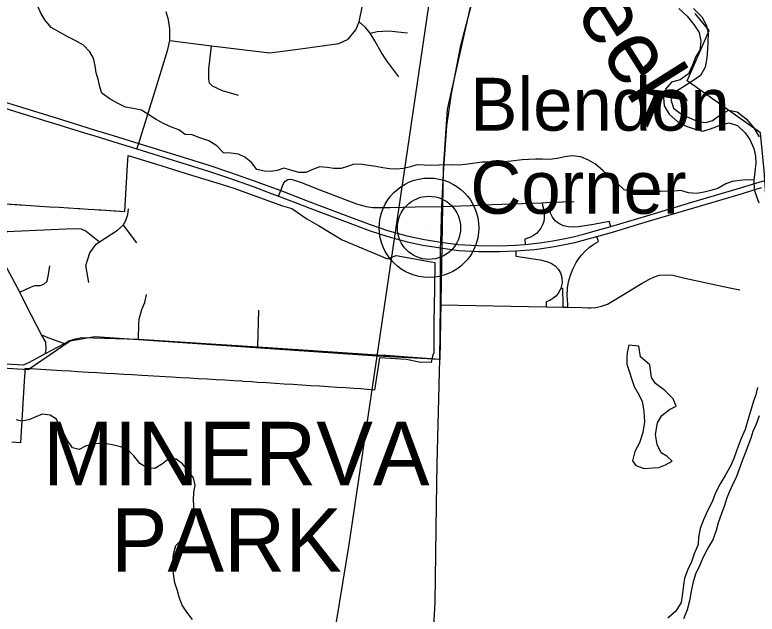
# Model space of a CAD drawing. Extents: x 0 to 34, y 0 to 22.
# Drawn here: x 4.322 to 5.431, y 17.262 to 18.158 of the extents above; entities that cross this region are included whole.
import ezdxf

# ---------------------------------------------------------------- set-up
doc = ezdxf.new("R2010")
doc.units = 0
for name, color, linetype in [('GM_X_City_Street', 7, 'Continuous'), ('GM_X_Corporation', 7, 'Continuous'), ('GM_X_Corporation_Text', 7, 'Continuous'), ('GM_X_County_Road', 7, 'Continuous'), ('GM_X_Interchange_Ramps', 7, 'Continuous'), ('GM_X_Major_River', 7, 'Continuous'), ('GM_X_Major_River_Text', 7, 'Continuous'), ('GM_X_Minor_Lake', 7, 'Continuous'), ('GM_X_Minor_River', 7, 'Continuous'), ('GM_X_Rail_Line', 7, 'Continuous'), ('GM_X_State_Route', 7, 'Continuous'), ('GM_X_Unincorporated', 7, 'Continuous'), ('GM_X_Unincorporated_Location', 7, 'Continuous'), ('GM_X_Unincorporated_Text', 7, 'Continuous')]:
    doc.layers.add(name, color=color, linetype=linetype)

msp = doc.modelspace()

# ---------------------------------------------------------------- linework, layer by layer
at = {"layer": 'GM_X_City_Street'}
for p, q in [((4.4835, 17.8434), (4.5036, 17.8167)), ((4.6848, 17.6616), (4.6864, 17.7161)), ((4.8762, 17.6488), (4.9564, 17.6428))]:
    msp.add_line(p, q, dxfattribs=at)
for points in [[(4.5531, 18.1191), (4.6157, 18.1112), (4.7026, 18.1008), (4.7486, 18.1067), (4.8056, 18.1149), (4.8197, 18.1211), (4.831, 18.1351), (4.836, 18.1472), (4.841, 18.1718), (4.8418, 18.1798), (4.8409, 18.1899), (4.8379, 18.199), (4.8314, 18.2115)], [(4.5042, 17.9572), (4.5069, 17.9656), (4.5119, 17.9816), (4.5348, 18.0557), (4.5503, 18.1058), (4.5531, 18.1191), (4.5532, 18.1367), (4.5514, 18.1504), (4.5477, 18.162)], [(4.8953, 18.0649), (4.8773, 18.0891), (4.8689, 18.1019), (4.8596, 18.119), (4.8524, 18.1303), (4.8455, 18.1387), (4.836, 18.1472)], [(4.8524, 18.1303), (4.863, 18.133), (4.8801, 18.1339), (4.9083, 18.1306)], [(4.6558, 18.0372), (4.6322, 18.0443), (4.6173, 18.051), (4.6127, 18.0556), (4.6115, 18.0616), (4.6114, 18.0764), (4.6157, 18.1112)], [(4.4323, 17.7577), (4.4278, 17.7828), (4.4338, 17.8018), (4.4432, 17.8147), (4.4485, 17.8183), (4.4754, 17.8357), (4.4835, 17.8434), (4.4876, 17.8501), (4.4907, 17.8592), (4.4915, 17.8676)], [(4.3041, 17.8282), (4.3102, 17.8339), (4.3209, 17.8342), (4.4092, 17.8384), (4.4207, 17.838), (4.4284, 17.8345), (4.4485, 17.8183)], [(4.3677, 17.6515), (4.3686, 17.6585), (4.3683, 17.6684), (4.3615, 17.6795), (4.3386, 17.724), (4.3292, 17.743), (4.3031, 17.7926), (4.2987, 17.8089), (4.2999, 17.8203), (4.3041, 17.8282)], [(4.3292, 17.743), (4.3444, 17.7504), (4.3517, 17.753), (4.3596, 17.7529), (4.365, 17.7552), (4.37, 17.7597), (4.3719, 17.7696), (4.3743, 17.7825)], [(4.5067, 17.6731), (4.5072, 17.6961), (4.5074, 17.703), (4.5117, 17.7175), (4.5159, 17.7277), (4.5187, 17.7395)], [(4.1637, 17.6439), (4.3257, 17.6351), (4.3348, 17.6348), (4.3429, 17.638), (4.3677, 17.6515), (4.3959, 17.6667), (4.4027, 17.6704), (4.4126, 17.6736), (4.4217, 17.6756), (4.5067, 17.6731), (4.6848, 17.6616), (4.8712, 17.6491), (4.8762, 17.6488)], [(4.3615, 17.6795), (4.3736, 17.6744), (4.3877, 17.6693), (4.3959, 17.6667)]]:
    msp.add_lwpolyline(points, dxfattribs=at)
at = {"layer": 'GM_X_Corporation'}
for points in [[(6.0874, 17.9568), (6.0027, 17.9627), (5.9083, 17.9706), (5.7991, 17.9758), (5.7562, 17.9753), (5.7213, 17.9698), (5.6189, 17.9397), (5.6023, 17.9358), (5.5774, 17.9293), (5.5387, 17.9169), (5.4879, 17.9006), (5.4786, 17.8937), (5.4653, 17.8843), (5.4439, 17.8811), (5.4411, 17.9254), (5.4406, 17.9301), (5.4357, 17.9811), (5.4171, 17.9943), (5.3261, 18.0588), (5.3588, 18.1342), (5.3379, 18.1599)], [(4.3075, 17.8751), (4.3287, 17.8738), (4.3312, 17.8736), (4.3452, 17.8727), (4.3594, 17.8718), (4.3738, 17.8709), (4.3882, 17.87), (4.402, 17.8691), (4.4163, 17.8682), (4.4187, 17.8681), (4.4312, 17.8673), (4.4415, 17.8666), (4.4472, 17.8663), (4.451, 17.866), (4.4861, 17.8639), (4.4901, 17.9332), (4.4912, 17.9474), (4.54, 17.9323), (4.5792, 17.9202), (4.6301, 17.9045), (4.6488, 17.8987), (4.7217, 17.872), (4.7356, 17.8684), (4.7579, 17.8529), (4.7752, 17.8426), (4.8109, 17.8216), (4.8784, 17.793), (4.8914, 17.798), (4.9437, 17.7885), (4.9493, 17.7875), (4.9485, 17.7487), (4.9475, 17.698), (4.9477, 17.673), (4.9478, 17.6514), (4.9462, 17.6498), (4.9436, 17.638), (4.9258, 17.6387), (4.9064, 17.6426), (4.8663, 17.6451), (4.8592, 17.5968), (4.8483, 17.5979), (4.8384, 17.5985), (4.8282, 17.5992), (4.8158, 17.6), (4.8034, 17.6008), (4.7899, 17.6016), (4.777, 17.6025), (4.7635, 17.6033), (4.7503, 17.6042), (4.7372, 17.605), (4.724, 17.6059), (4.7109, 17.6067), (4.6975, 17.6076), (4.6843, 17.6084), (4.6757, 17.6091), (4.6622, 17.6099), (4.6602, 17.61), (4.649, 17.6107), (4.6357, 17.6115), (4.6224, 17.6123), (4.6092, 17.613), (4.5959, 17.6138), (4.5828, 17.6146), (4.5696, 17.6153), (4.5559, 17.6161), (4.5466, 17.6166), (4.5203, 17.6181), (4.5111, 17.6187), (4.4978, 17.6194), (4.4846, 17.6202), (4.4707, 17.621), (4.4577, 17.6218), (4.4449, 17.6226), (4.4318, 17.6233), (4.4156, 17.6243), (4.4052, 17.6249), (4.3919, 17.6257), (4.337, 17.6289), (4.3367, 17.6237), (4.3358, 17.61), (4.3301, 17.518), (4.3172, 17.5189)], [(4.3075, 17.8751), (4.3254, 17.874), (4.3312, 17.8736), (4.3452, 17.8727), (4.3594, 17.8718), (4.3738, 17.8709), (4.3882, 17.87), (4.402, 17.8691), (4.4163, 17.8682), (4.4187, 17.8681), (4.4312, 17.8673), (4.4415, 17.8666), (4.4472, 17.8663), (4.451, 17.866), (4.4702, 17.8648), (4.4861, 17.8639), (4.4901, 17.9332), (4.4912, 17.9474), (4.54, 17.9323), (4.5792, 17.9202), (4.6301, 17.9045), (4.6488, 17.8987), (4.7217, 17.872), (4.7356, 17.8684), (4.7579, 17.8529), (4.7752, 17.8426), (4.8109, 17.8216), (4.8784, 17.793), (4.8914, 17.798), (4.9437, 17.7885), (4.9493, 17.7875), (4.9485, 17.7487), (4.9475, 17.698), (4.9477, 17.673), (4.9478, 17.6514), (4.9462, 17.6498), (4.9436, 17.638), (4.9258, 17.6387), (4.9064, 17.6426), (4.8663, 17.6451), (4.8592, 17.5968), (4.8483, 17.5979), (4.8384, 17.5985), (4.8282, 17.5992), (4.8158, 17.6), (4.8034, 17.6008), (4.7899, 17.6016), (4.777, 17.6025), (4.7635, 17.6033), (4.7503, 17.6042), (4.7372, 17.605), (4.724, 17.6059), (4.7109, 17.6067), (4.6975, 17.6076), (4.6843, 17.6084), (4.6757, 17.6091), (4.6622, 17.6099), (4.6602, 17.61), (4.649, 17.6107), (4.6357, 17.6115), (4.6224, 17.6123), (4.6092, 17.613), (4.5959, 17.6138), (4.5828, 17.6146), (4.5696, 17.6153), (4.5559, 17.6161), (4.5466, 17.6166), (4.5203, 17.6181), (4.5111, 17.6187), (4.4978, 17.6194), (4.4846, 17.6202), (4.4707, 17.621), (4.4577, 17.6218), (4.4449, 17.6226), (4.4318, 17.6233), (4.4156, 17.6243), (4.4052, 17.6249), (4.3919, 17.6257), (4.337, 17.6289), (4.3367, 17.6237), (4.3358, 17.61), (4.3301, 17.518), (4.3172, 17.5189)]]:
    msp.add_lwpolyline(points, dxfattribs=at)
at = {"layer": 'GM_X_County_Road'}
for p, q in [((5.0024, 17.8727), (5.0345, 17.874)), ((4.9576, 17.7243), (5.1155, 17.7215))]:
    msp.add_line(p, q, dxfattribs=at)
for points in [[(4.7155, 17.8866), (4.719, 17.8952), (4.7232, 17.9054), (4.7255, 17.9089), (4.7296, 17.9114), (4.7341, 17.9119), (4.7408, 17.9102), (4.7484, 17.9074), (4.7776, 17.8963), (4.8135, 17.8823), (4.8324, 17.8754)], [(4.8324, 17.8754), (4.8354, 17.8743), (4.8466, 17.8713), (4.8565, 17.8699), (4.8824, 17.8699), (4.92, 17.8705), (4.9594, 17.8711), (5.0024, 17.8727)], [(5.0345, 17.874), (5.1096, 17.8768), (5.1226, 17.8775), (5.1575, 17.8787)], [(5.178, 17.72), (5.1821, 17.7198), (5.1895, 17.7205), (5.198, 17.7221), (5.2072, 17.7253), (5.2219, 17.7341), (5.259, 17.7564), (5.2686, 17.762), (5.2774, 17.7661), (5.2843, 17.7686), (5.2935, 17.7692), (5.3049, 17.7684), (5.3228, 17.7643), (5.3873, 17.7504), (5.4047, 17.7465)], [(5.1155, 17.7215), (5.1404, 17.721), (5.1479, 17.7208), (5.1687, 17.7203), (5.178, 17.72)]]:
    msp.add_lwpolyline(points, dxfattribs=at)
at = {"layer": 'GM_X_Interchange_Ramps'}
for points in [[(5.1096, 17.8768), (5.1098, 17.8734), (5.1122, 17.8657), (5.1125, 17.8605), (5.1126, 17.8542), (5.112, 17.849), (5.1102, 17.8438), (5.1077, 17.8388), (5.1047, 17.8348), (5.1008, 17.8311), (5.0967, 17.8279), (5.0922, 17.8255), (5.0883, 17.8239), (5.0834, 17.8226), (5.0839, 17.8144)], [(5.2119, 17.8414), (5.2097, 17.8488), (5.186, 17.8444), (5.1638, 17.841), (5.157, 17.8404), (5.1487, 17.8409), (5.1413, 17.8424), (5.1344, 17.8457), (5.1291, 17.85), (5.125, 17.8552), (5.1219, 17.8612), (5.1212, 17.8667), (5.1218, 17.8725), (5.1226, 17.8775)], [(5.1479, 17.7208), (5.1476, 17.7255), (5.1467, 17.7379), (5.1471, 17.7492), (5.1489, 17.7588), (5.1516, 17.7685), (5.1551, 17.7774), (5.1603, 17.7874), (5.1645, 17.7937), (5.1684, 17.7985), (5.1738, 17.8043), (5.1803, 17.8103), (5.1865, 17.815), (5.1934, 17.819), (5.1913, 17.8262)], [(5.0702, 17.805), (5.0704, 17.797), (5.1066, 17.7915), (5.1161, 17.7892), (5.123, 17.7864), (5.129, 17.7827), (5.1336, 17.7778), (5.1368, 17.7722), (5.139, 17.7649), (5.1394, 17.7571), (5.1376, 17.7494), (5.1358, 17.7459), (5.1332, 17.7413), (5.1299, 17.7372), (5.1255, 17.7336), (5.1207, 17.7308), (5.1154, 17.7288), (5.1155, 17.7215)], [(5.1376, 17.7494), (5.1399, 17.7491), (5.1404, 17.7253), (5.1404, 17.721)]]:
    msp.add_lwpolyline(points, dxfattribs=at)
at = {"layer": 'GM_X_Major_River'}
for points in [[(5.3137, 18.1672), (5.3262, 18.1557), (5.336, 18.1431), (5.3442, 18.1313), (5.3465, 18.118), (5.3449, 18.1051), (5.3388, 18.0953), (5.3338, 18.0824), (5.328, 18.0695), (5.3154, 18.0605), (5.3029, 18.0571), (5.2938, 18.0465), (5.2907, 18.034), (5.2917, 18.0215), (5.2993, 18.0093), (5.3121, 17.9978), (5.3246, 17.9913), (5.3382, 17.9867), (5.3488, 17.984), (5.361, 17.9874), (5.3754, 17.993), (5.3887, 17.9964), (5.4012, 17.9925), (5.4125, 17.9811), (5.4197, 17.9715), (5.4257, 17.9578), (5.4283, 17.9464), (5.4286, 17.9362), (5.427, 17.9229), (5.4255, 17.9104), (5.4262, 17.8967), (5.4295, 17.8864), (5.4329, 17.8769)], [(5.3353, 18.1671), (5.3478, 18.1549), (5.3549, 18.1419), (5.3575, 18.1294), (5.3571, 18.1165), (5.3563, 18.1062), (5.3554, 18.0933), (5.3531, 18.0797), (5.3458, 18.0672), (5.3329, 18.0581), (5.3207, 18.0502), (5.3078, 18.0423), (5.3016, 18.0309), (5.3058, 18.0184), (5.3178, 18.0092), (5.3296, 18.0035), (5.3421, 17.9985), (5.3542, 17.9969), (5.3641, 17.9999), (5.3763, 18.0089), (5.3884, 18.015), (5.4009, 18.0126), (5.4142, 18.0023), (5.4258, 17.989), (5.4337, 17.9753)], [(5.4311, 17.6005), (5.4284, 17.5895), (5.425, 17.5801), (5.4211, 17.5668), (5.4169, 17.552), (5.4126, 17.538), (5.4069, 17.5243), (5.4026, 17.5141), (5.3992, 17.5046), (5.3957, 17.4944), (5.3911, 17.4841), (5.3827, 17.469), (5.3754, 17.4565), (5.3685, 17.4432), (5.3632, 17.43), (5.3566, 17.4163), (5.3505, 17.4031), (5.3455, 17.3902), (5.3432, 17.3769), (5.3424, 17.3663), (5.3366, 17.3523), (5.3327, 17.3401), (5.327, 17.3288)], [(5.4336, 17.5584), (5.429, 17.5459), (5.424, 17.5349), (5.4213, 17.525), (5.4174, 17.5144), (5.4136, 17.5049), (5.4082, 17.4909), (5.4036, 17.4788), (5.3998, 17.4678), (5.394, 17.4553), (5.389, 17.4443), (5.3848, 17.4341), (5.3817, 17.4242), (5.3771, 17.4109), (5.3725, 17.3984), (5.3694, 17.387), (5.3644, 17.373), (5.3583, 17.3632), (5.3529, 17.353), (5.3483, 17.3435), (5.3445, 17.334), (5.3387, 17.3219), (5.3349, 17.3105), (5.3321, 17.2965), (5.3294, 17.2817), (5.3263, 17.2684), (5.3206, 17.2548)], [(5.327, 17.3288), (5.322, 17.3155), (5.3204, 17.306), (5.3189, 17.2931), (5.3169, 17.2795), (5.3089, 17.2666), (5.2974, 17.256)]]:
    msp.add_lwpolyline(points, dxfattribs=at)
at = {"layer": 'GM_X_Minor_Lake'}
for points in [[(5.2493, 17.484), (5.2618, 17.4797), (5.2755, 17.4807), (5.2838, 17.481), (5.2937, 17.485), (5.3036, 17.4906), (5.2957, 17.4979), (5.2871, 17.5029), (5.2811, 17.5155), (5.2786, 17.5304), (5.2818, 17.5478), (5.288, 17.5587), (5.2998, 17.5677), (5.3094, 17.5726), (5.3053, 17.584), (5.2929, 17.5963), (5.2786, 17.6067), (5.2726, 17.6158), (5.2701, 17.6345), (5.2566, 17.6467), (5.2541, 17.6627), (5.2389, 17.664), (5.2362, 17.653), (5.2361, 17.645), (5.236, 17.6356)], [(5.2493, 17.484), (5.2618, 17.4797), (5.2755, 17.4807), (5.2838, 17.481), (5.2937, 17.485), (5.3036, 17.4906), (5.2957, 17.4979), (5.2871, 17.5029), (5.2811, 17.5155), (5.2786, 17.5304), (5.2818, 17.5478), (5.288, 17.5587), (5.2998, 17.5677), (5.3094, 17.5726), (5.3053, 17.584), (5.2929, 17.5963), (5.2786, 17.6067), (5.2726, 17.6158), (5.2701, 17.6345), (5.2566, 17.6467), (5.2541, 17.6627), (5.2389, 17.664), (5.2362, 17.653), (5.2361, 17.645), (5.236, 17.6348)], [(5.236, 17.6356), (5.2467, 17.602), (5.2545, 17.5891), (5.259, 17.5799), (5.2611, 17.5651), (5.2621, 17.5495), (5.26, 17.5332), (5.255, 17.5181), (5.248, 17.5052), (5.2445, 17.4912)], [(5.2445, 17.4912), (5.2493, 17.484)]]:
    msp.add_lwpolyline(points, dxfattribs=at)
at = {"layer": 'GM_X_Minor_River'}
for points in [[(4.3665, 18.1501), (4.3609, 18.1604), (4.3557, 18.1715), (4.3517, 18.181), (4.3468, 18.1917), (4.3428, 18.2031), (4.3394, 18.2145), (4.3365, 18.2271), (4.3363, 18.2393), (4.3341, 18.2518), (4.3308, 18.2617), (4.3286, 18.272), (4.3264, 18.2819), (4.3246, 18.2948), (4.3228, 18.3066), (4.3184, 18.3184)], [(5.4255, 17.9106), (5.4142, 17.9112), (5.4047, 17.9101), (5.3933, 17.9087), (5.3838, 17.905), (5.372, 17.8983), (5.3613, 17.895), (5.3515, 17.8928), (5.3401, 17.8906), (5.3283, 17.8915), (5.3166, 17.895), (5.3067, 17.894), (5.2965, 17.8941), (5.2863, 17.8934), (5.2741, 17.8935), (5.2643, 17.8921), (5.2529, 17.8929), (5.2419, 17.8934), (5.2321, 17.8962), (5.2212, 17.9065), (5.2107, 17.9154), (5.2005, 17.9246), (5.1889, 17.9346), (5.1787, 17.9407), (5.1674, 17.9454), (5.1545, 17.947), (5.1431, 17.9456), (5.1317, 17.9431), (5.1203, 17.9413), (5.1097, 17.9418), (5.0999, 17.9422), (5.0896, 17.9416), (5.0798, 17.9409), (5.0631, 17.9392), (5.0517, 17.9381), (5.0422, 17.9386), (5.032, 17.9376), (5.0199, 17.9373), (4.9986, 17.9345), (4.9853, 17.9331), (4.9755, 17.9335), (4.955, 17.933), (4.944, 17.9327), (4.933, 17.9328), (4.9224, 17.9333), (4.9129, 17.9303), (4.9023, 17.9282), (4.8917, 17.9271), (4.8814, 17.9276), (4.8716, 17.9288), (4.861, 17.9312), (4.8508, 17.9325), (4.8406, 17.9341), (4.8284, 17.9346), (4.8189, 17.9312), (4.8091, 17.9279), (4.7984, 17.928), (4.7882, 17.9296), (4.7772, 17.9305), (4.7677, 17.9272), (4.7563, 17.922), (4.7461, 17.9221), (4.734, 17.9256), (4.7234, 17.9287), (4.7139, 17.925), (4.7044, 17.9236), (4.6946, 17.9241), (4.6832, 17.9264), (4.6754, 17.9368), (4.6656, 17.9448), (4.6558, 17.9495), (4.6444, 17.9511), (4.6334, 17.9516), (4.6233, 17.962), (4.6116, 17.9693), (4.598, 17.974), (4.5867, 17.9783), (4.5764, 17.9787), (4.5667, 17.986), (4.5557, 17.9899), (4.544, 17.9954), (4.5331, 18.0012), (4.5218, 18.0081), (4.5112, 18.0154), (4.4987, 18.0178), (4.487, 18.0198), (4.4772, 18.0249), (4.464, 18.0318), (4.4519, 18.0407), (4.4486, 18.0502), (4.4468, 18.0597), (4.4435, 18.0711), (4.4417, 18.0814), (4.4395, 18.0928), (4.4336, 18.1024), (4.4246, 18.1123), (4.4117, 18.1193), (4.4012, 18.1247), (4.3883, 18.1317), (4.3763, 18.1386), (4.3665, 18.1501)], [(4.4695, 17.5145), (4.4593, 17.5165), (4.4476, 17.517), (4.4373, 17.516), (4.4274, 17.513), (4.4179, 17.5082), (4.4081, 17.5106), (4.4006, 17.5216), (4.3954, 17.5316), (4.3887, 17.5426), (4.3842, 17.5533), (4.3744, 17.5595), (4.3627, 17.5607), (4.3532, 17.5567), (4.3429, 17.5526), (4.3319, 17.5504), (4.3236, 17.5524)], [(4.5873, 17.254), (4.5787, 17.2647), (4.5716, 17.2754), (4.5675, 17.2872), (4.5646, 17.2968), (4.5609, 17.3086), (4.5591, 17.3181), (4.558, 17.331), (4.5578, 17.3405), (4.5586, 17.3515), (4.5625, 17.3644), (4.5728, 17.3753), (4.582, 17.3866), (4.5871, 17.3968), (4.5906, 17.4078), (4.5895, 17.4173), (4.5885, 17.4325), (4.5894, 17.4439), (4.591, 17.4545), (4.5888, 17.4659), (4.581, 17.4755), (4.5723, 17.4866), (4.5626, 17.4935), (4.5523, 17.4944), (4.5424, 17.4865), (4.531, 17.4794), (4.52, 17.4799), (4.5087, 17.4872), (4.4997, 17.4987), (4.4895, 17.5083), (4.4797, 17.5122), (4.4695, 17.5145)]]:
    msp.add_lwpolyline(points, dxfattribs=at)
at = {"layer": 'GM_X_Rail_Line'}
for points in [[(4.8023, 17.2505), (4.8213, 17.366), (4.863, 17.6474), (4.9037, 17.9242), (4.9925, 18.5268), (4.995, 18.5559), (4.9836, 19.0836), (4.9859, 19.7538), (4.9926, 19.9029), (5.013, 20.2642), (5.0202, 20.3863), (5.0504, 20.9)], [(5.013, 20.2642), (5.1449, 19.8014), (5.1573, 19.7292), (5.1597, 19.509), (5.1344, 19.0127), (5.1201, 18.6386), (5.0674, 18.4202), (5.0194, 18.2471), (4.9676, 18.0163), (4.9615, 17.9273), (4.9565, 17.6426), (4.863, 17.6474)], [(4.863, 17.6474), (4.4415, 17.6766), (4.4045, 17.6698), (4.3418, 17.6273), (4.1638, 17.6386), (4.1351, 17.6177), (4.0032, 17.5899), (3.7805, 17.5103), (3.7355, 17.4587), (3.7202, 17.4495), (3.6121, 15.7571)]]:
    msp.add_lwpolyline(points, dxfattribs=at)
at = {"layer": 'GM_X_State_Route'}
msp.add_line((4.9564, 17.6428), (4.9576, 17.7243), dxfattribs=at)
for points in [[(4.9594, 17.8711), (4.9619, 17.9208), (4.9669, 17.9919), (4.9742, 18.0398), (4.9879, 18.1116), (5.0132, 18.2094), (5.0472, 18.3361)], [(3.8614, 18.152), (3.8721, 18.1492), (3.9253, 18.1354), (3.9778, 18.1215), (4.0384, 18.1056), (4.0638, 18.0991), (4.1059, 18.0879), (4.1364, 18.0794), (4.1928, 18.0626), (4.2629, 18.041), (4.3202, 18.0232), (4.3838, 18.0037), (4.4388, 17.9865), (4.4689, 17.9772), (4.5069, 17.9656)], [(3.8605, 18.1433), (3.8701, 18.1408), (3.9233, 18.1269), (3.9758, 18.1131), (4.0363, 18.0972), (4.0618, 18.0907), (4.1033, 18.0796), (4.1342, 18.0711), (4.1931, 18.0535), (4.2603, 18.0326), (4.3211, 18.0139), (4.3792, 17.9959), (4.3811, 17.9953), (4.4274, 17.981), (4.44, 17.9772), (4.4696, 17.968), (4.5042, 17.9572), (4.544, 17.9449), (4.5793, 17.9342), (4.6112, 17.9239), (4.641, 17.914), (4.678, 17.9009), (4.7061, 17.8902)], [(4.5069, 17.9656), (4.5474, 17.953), (4.5813, 17.9425), (4.6114, 17.9329), (4.6442, 17.9219), (4.6778, 17.9102), (4.719, 17.8952)], [(4.719, 17.8952), (4.7587, 17.8796), (4.811, 17.8597), (4.8526, 17.8441), (4.8786, 17.8355), (4.9073, 17.8276), (4.9335, 17.8218), (4.958, 17.8179), (4.9841, 17.8142), (5.0139, 17.8127), (5.0453, 17.8125), (5.0696, 17.8135), (5.0839, 17.8144), (5.106, 17.8167), (5.1256, 17.8197), (5.1412, 17.8227), (5.156, 17.8261), (5.1732, 17.8302), (5.1888, 17.8347), (5.2119, 17.8414), (5.2656, 17.8575), (5.3332, 17.8777), (5.4008, 17.8976), (5.445, 17.911)], [(5.239, 17.8403), (5.2484, 17.8432), (5.2683, 17.8491), (5.3359, 17.8692), (5.4035, 17.8893), (5.4373, 17.8996)], [(4.7061, 17.8902), (4.7155, 17.8866), (4.7548, 17.8718)], [(4.7548, 17.8718), (4.7587, 17.8703), (4.8101, 17.8508), (4.8528, 17.8349), (4.8789, 17.8264), (4.9077, 17.8184), (4.9313, 17.8134), (4.9547, 17.8097)], [(4.9577, 17.8024), (4.9578, 17.8092), (4.958, 17.8179), (4.9594, 17.8711)], [(4.9547, 17.8097), (4.9578, 17.8092), (4.9846, 17.8055), (5.0143, 17.804), (5.0457, 17.8038), (5.0702, 17.805), (5.0843, 17.8061), (5.0979, 17.8071), (5.1086, 17.8085), (5.1281, 17.8116), (5.1585, 17.8176), (5.1913, 17.8262), (5.2144, 17.833), (5.239, 17.8403)], [(4.9576, 17.7243), (4.9575, 17.7639), (4.9577, 17.8024)], [(4.9517, 17.4254), (4.9526, 17.4866), (4.9564, 17.6428)], [(4.8958, 17.0912), (4.9191, 17.1327), (4.9371, 17.1698), (4.9426, 17.1953), (4.9464, 17.2184), (4.9495, 17.2794), (4.9517, 17.4254)]]:
    msp.add_lwpolyline(points, dxfattribs=at)
at = {"layer": 'GM_X_Unincorporated'}
for radius in [0.0744, 0.0472]:
    msp.add_circle((4.9405, 17.8394), radius, dxfattribs=at)
at = {"layer": 'GM_X_Unincorporated_Location'}
msp.add_line((4.9405, 17.8394), (4.9405, 17.8394), dxfattribs=at)

# ---------------------------------------------------------------- texts
at = {"layer": 'GM_X_Corporation_Text'}
for s, p in [('MINERVA', (4.3641, 17.4547)), ('PARK', (4.4654, 17.3254))]:
    msp.add_text(s, height=0.0947, rotation=0, dxfattribs=at).set_placement(p)
at = {"layer": 'GM_X_Major_River_Text'}
msp.add_text('Creek', height=0.0947, rotation=302.2062, dxfattribs=at).set_placement((5.0868, 18.275))
at = {"layer": 'GM_X_Unincorporated_Text'}
for s, p in [('Blendon', (5.0021, 17.9846)), ('Corner', (5.0021, 17.8604))]:
    msp.add_text(s, height=0.07898, rotation=0, dxfattribs=at).set_placement(p)

doc.saveas('drawing.dxf')
